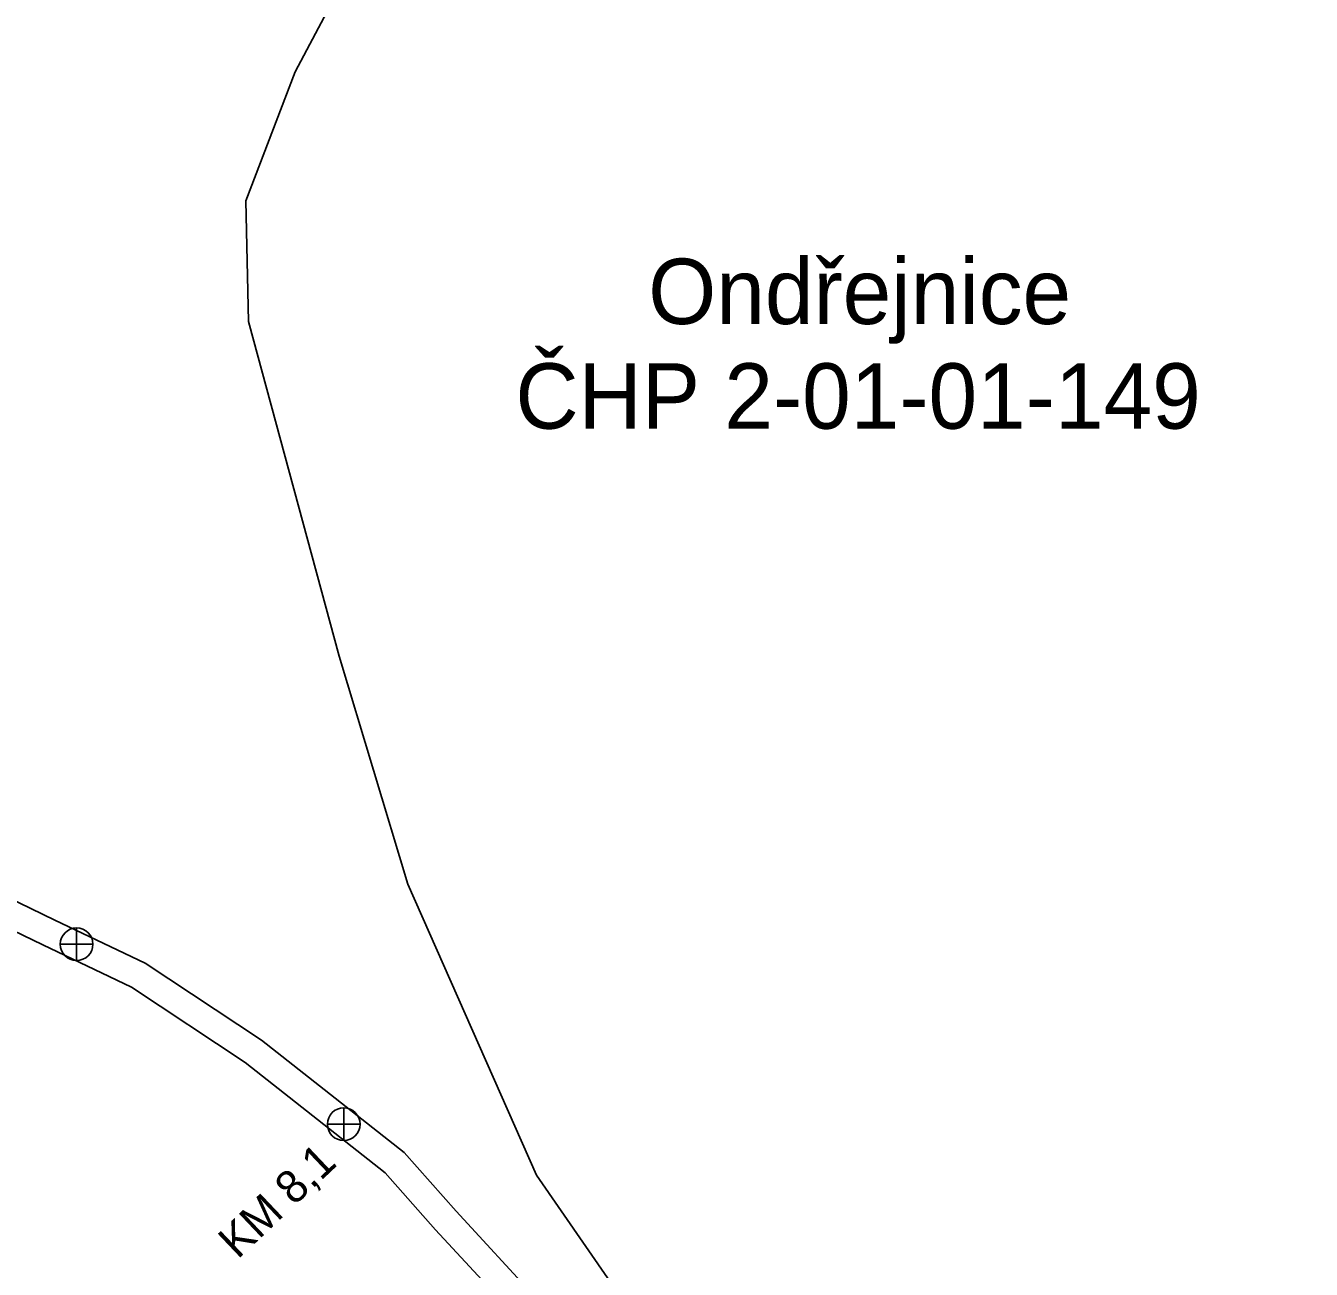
# Model space of a CAD drawing. Extents: x -478464 to -472469, y -1118040 to -1113785.
# Drawn here: x -476356.8 to -475963.6, y -1116297 to -1115916.7 of the extents above; entities that cross this region are included whole.
import ezdxf

# ---------------------------------------------------------------- set-up
doc = ezdxf.new("R2010")
doc.units = 0
for name, color, linetype in [('povodí', 7, 'Continuous'), ('silnice', 7, 'Continuous'), ('staničení toku', 7, 'Continuous'), ('vodní plochy', 7, 'Continuous')]:
    doc.layers.add(name, color=color, linetype=linetype)

msp = doc.modelspace()

# ---------------------------------------------------------------- linework, layer by layer
at = {"layer": 'silnice'}
msp.add_lwpolyline([(-475903.982, -1117378.322), (-475889.519, -1117318.176), (-475888.389, -1117289.008), (-475895.395, -1117261.196), (-475916.638, -1117209.19), (-475969.886, -1117075.455), (-476021.05, -1116948.737), (-476052.923, -1116863.979), (-476081.44, -1116727.192), (-476114.99, -1116491.378), (-476128.411, -1116405.781), (-476137.637, -1116368.017), (-476162.8, -1116322.7), (-476200.543, -1116268.153), (-476239.965, -1116179.199), (-476260.934, -1116109.546), (-476288.613, -1116007.164), (-476289.451, -1115970.24), (-476274.354, -1115930.798), (-476261.922, -1115907.288), (-476366.595, -1115823.727)], dxfattribs=at)
at = {"layer": 'staničení toku'}
for p, q in [((-476341.214, -1116192.579), (-476341.214, -1116202.579)), ((-476336.214, -1116197.579), (-476346.214, -1116197.579)), ((-476259.519, -1116247.607), (-476259.519, -1116257.607)), ((-476254.519, -1116252.607), (-476264.519, -1116252.607))]:
    msp.add_line(p, q, dxfattribs=at)
for centre in [(-476341.214, -1116197.579), (-476259.519, -1116252.607)]:
    msp.add_circle(centre, 5, dxfattribs=at)
at = {"layer": 'vodní plochy'}
for points in [[(-476200.558, -1116305.872), (-476225.178, -1116279.205), (-476240.993, -1116261.287), (-476284.697, -1116226.903), (-476320.29, -1116203.316), (-476347.924, -1116190.183), (-476388.083, -1116170.718)], [(-476391.698, -1116178.366), (-476351.584, -1116197.809), (-476324.463, -1116210.698), (-476289.656, -1116233.764), (-476246.827, -1116267.46), (-476231.457, -1116284.873), (-476206.824, -1116311.554)]]:
    msp.add_lwpolyline(points, dxfattribs=at)

# ---------------------------------------------------------------- texts
at = {"layer": 'povodí'}
for s, p in [('Ondřejnice', (-476166.394, -1116007.946)), ('ČHP 2-01-01-149', (-476207.017, -1116039.946))]:
    msp.add_text(s, height=20, rotation=359.99999, dxfattribs=at).set_placement(p)
at = {"layer": 'staničení toku'}
msp.add_text('KM 8,1', height=10, rotation=43.47786, dxfattribs=at).set_placement((-476291.939, -1116294.118))

doc.saveas('drawing.dxf')
